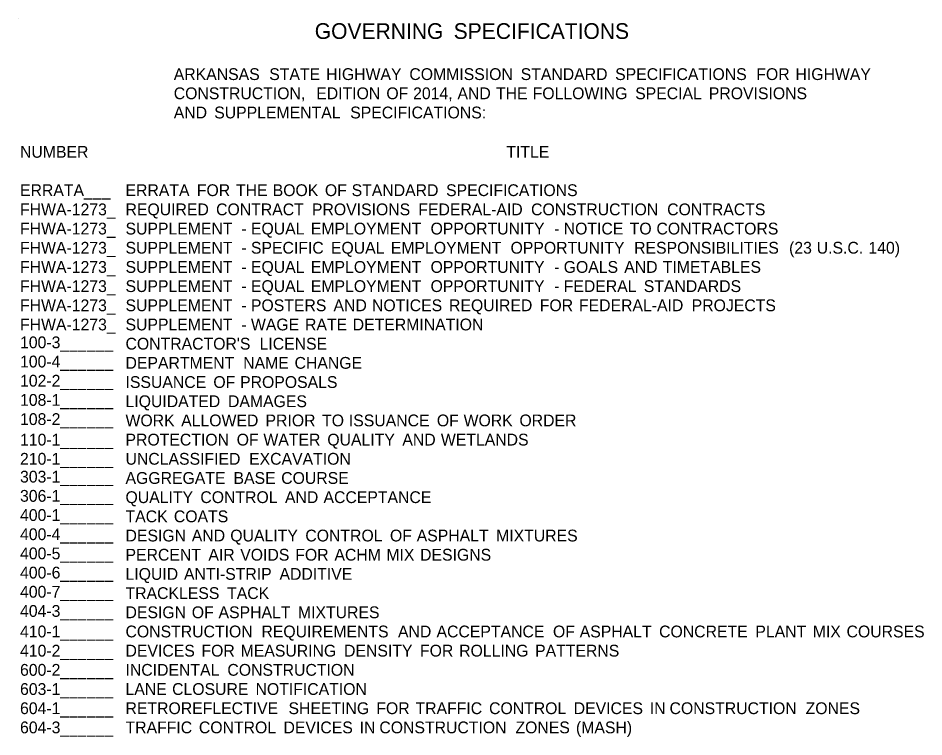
# Model space of a CAD drawing. Extents: x 1930579 to 1935504, y 596431 to 597414.
# Drawn here: x 1934071 to 1934624, y 596955 to 597393 of the extents above; entities that cross this region are included whole.
import ezdxf

# ---------------------------------------------------------------- set-up
doc = ezdxf.new("R2010")
doc.units = 0
doc.layers.add('Default', color=7, linetype='Continuous')
doc.layers.add('R_Border', color=7, linetype='Continuous')

msp = doc.modelspace()

# ---------------------------------------------------------------- linework, layer by layer
at = {"layer": 'R_Border'}
msp.add_line((1934071.42, 597393.18), (1934071.42, 597393.18), dxfattribs=at)

# ---------------------------------------------------------------- texts
at = {"layer": 'Default'}
for s, height, p in [('GOVERNING', 9.6, (1934252.37, 597380.48)), (' SPECIFICATIONS', 9.6, (1934333.54, 597380.48)), ('           ARKANSAS', 7.2, (1934136.94, 597355.42)), (' STATE', 7.2, (1934221.94, 597355.42)), (' HIGHWAY', 7.2, (1934256.63, 597355.42)), (' COMMISSION', 7.2, (1934307.41, 597355.42)), (' STANDARD', 7.2, (1934375.33, 597355.42)), (' SPECIFICATIONS', 7.2, (1934432.93, 597355.42)), (' FOR', 7.2, (1934519.05, 597355.42)), (' HIGHWAY', 7.2, (1934542.95, 597355.42)), ('           CONSTRUCTION,', 7.2, (1934136.94, 597343.72)), (' EDITION', 7.2, (1934250.61, 597343.72)), (' OF', 7.2, (1934293.38, 597343.72)), (' 2014,', 7.2, (1934309.69, 597343.72)), (' AND', 7.2, (1934336.75, 597343.72)), (' THE', 7.2, (1934360.25, 597343.72)), (' FOLLOWING', 7.2, (1934382.63, 597343.72)), (' SPECIAL', 7.2, (1934445.15, 597343.72)), (' PROVISIONS', 7.2, (1934490.08, 597343.72)), ('           AND', 7.2, (1934136.94, 597332.02)), (' SUPPLEMENTAL', 7.2, (1934188.37, 597332.02)), (' SPECIFICATIONS:', 7.2, (1934271.32, 597332.02)), ('NUMBER', 7.2, (1934072.59, 597308.04)), ('TITLE', 7.2, (1934369.21, 597308.04)), ('ERRATA___', 7.2, (1934072.59, 597284.64)), ('ERRATA', 7.2, (1934136.94, 597284.64)), (' FOR', 7.2, (1934177.77, 597284.64)), (' THE', 7.2, (1934201.67, 597284.64)), (' BOOK', 7.2, (1934224.04, 597284.64)), (' OF', 7.2, (1934255.89, 597284.64)), (' STANDARD', 7.2, (1934272.19, 597284.64)), (' SPECIFICATIONS', 7.2, (1934329.79, 597284.64)), ('FHWA-1273_', 7.2, (1934072.59, 597272.94)), ('REQUIRED', 7.2, (1934136.94, 597272.94)), (' CONTRACT', 7.2, (1934189.51, 597272.94)), (' PROVISIONS', 7.2, (1934247.99, 597272.94)), (' FEDERAL-AID', 7.2, (1934312.88, 597272.94)), (' CONSTRUCTION', 7.2, (1934381.65, 597272.94)), (' CONTRACTS', 7.2, (1934464.67, 597272.94)), ('FHWA-1273_', 7.2, (1934072.59, 597261.24)), ('SUPPLEMENT', 7.2, (1934136.94, 597261.24)), (' EQUAL', 7.2, (1934210.77, 597261.24)), (' EMPLOYMENT', 7.2, (1934247.32, 597261.24)), (' OPPORTUNITY', 7.2, (1934320.34, 597261.24)), (' NOTICE', 7.2, (1934401.56, 597261.24)), (' TO', 7.2, (1934441.82, 597261.24)), (' CONTRACTORS', 7.2, (1934458.14, 597261.24)), (' -', 7.2, (1934204.95, 597261.24)), (' -', 7.2, (1934395.73, 597261.24)), ('FHWA-1273_', 7.2, (1934072.59, 597249.54)), ('SUPPLEMENT', 7.2, (1934136.94, 597249.54)), (' -', 7.2, (1934204.95, 597249.54)), (' SPECIFIC', 7.2, (1934210.77, 597249.54)), (' EQUAL', 7.2, (1934259.57, 597249.54)), (' EMPLOYMENT', 7.2, (1934296.11, 597249.54)), (' OPPORTUNITY', 7.2, (1934369.14, 597249.54)), (' RESPONSIBILITIES', 7.2, (1934444.52, 597249.54)), (' (23', 7.2, (1934539.04, 597249.54)), (' U.S.C.', 7.2, (1934555.91, 597249.54)), (' 140)', 7.2, (1934587.45, 597249.54)), ('FHWA-1273_', 7.2, (1934072.59, 597237.84)), ('SUPPLEMENT', 7.2, (1934136.94, 597237.84)), (' -', 7.2, (1934204.95, 597237.84)), (' EQUAL', 7.2, (1934210.77, 597237.84)), (' EMPLOYMENT', 7.2, (1934247.32, 597237.84)), (' OPPORTUNITY', 7.2, (1934320.34, 597237.84)), (' -', 7.2, (1934395.73, 597237.84)), (' GOALS', 7.2, (1934401.56, 597237.84)), (' AND', 7.2, (1934438.49, 597237.84)), (' TIMETABLES', 7.2, (1934461.99, 597237.84)), ('FHWA-1273_', 7.2, (1934072.59, 597226.14)), ('SUPPLEMENT', 7.2, (1934136.94, 597226.14)), (' EQUAL', 7.2, (1934210.77, 597226.14)), (' EMPLOYMENT', 7.2, (1934247.32, 597226.14)), (' OPPORTUNITY', 7.2, (1934320.34, 597226.14)), (' FEDERAL', 7.2, (1934401.56, 597226.14)), (' STANDARDS', 7.2, (1934450.4, 597226.14)), (' -', 7.2, (1934204.95, 597226.14)), (' -', 7.2, (1934395.73, 597226.14)), ('FHWA-1273_', 7.2, (1934072.59, 597214.44)), ('SUPPLEMENT', 7.2, (1934136.94, 597214.44)), (' POSTERS', 7.2, (1934210.77, 597214.44)), (' AND', 7.2, (1934261.13, 597214.44)), (' NOTICES', 7.2, (1934284.62, 597214.44)), (' REQUIRED', 7.2, (1934331.61, 597214.44)), (' FOR', 7.2, (1934386.97, 597214.44)), (' FEDERAL-AID', 7.2, (1934410.87, 597214.44)), (' PROJECTS', 7.2, (1934479.64, 597214.44)), (' -', 7.2, (1934204.95, 597214.44)), ('FHWA-1273_', 7.2, (1934072.59, 597202.74)), ('SUPPLEMENT', 7.2, (1934136.94, 597202.74)), (' WAGE', 7.2, (1934210.77, 597202.74)), (' RATE', 7.2, (1934243.77, 597202.74)), (' DETERMINATION', 7.2, (1934272.86, 597202.74)), (' -', 7.2, (1934204.95, 597202.74)), ('100-3______', 7.2, (1934072.59, 597191.85)), ("CONTRACTOR'S", 7.2, (1934136.94, 597191.04)), (' LICENSE', 7.2, (1934216.03, 597191.04)), ('100-4______', 7.2, (1934072.59, 597180.15)), ('DEPARTMENT', 7.2, (1934136.94, 597179.34)), (' NAME', 7.2, (1934206.06, 597179.34)), (' CHANGE', 7.2, (1934237.38, 597179.34)), ('102-2______', 7.2, (1934072.59, 597168.45)), ('ISSUANCE', 7.2, (1934136.94, 597167.64)), (' OF', 7.2, (1934187.84, 597167.64)), (' PROPOSALS', 7.2, (1934204.15, 597167.64)), ('108-1______', 7.2, (1934072.59, 597156.75)), ('LIQUIDATED', 7.2, (1934136.94, 597155.94)), (' DAMAGES', 7.2, (1934196.78, 597155.94)), ('108-2______', 7.2, (1934072.59, 597145.05)), ('WORK', 7.2, (1934136.94, 597144.24)), (' ALLOWED', 7.2, (1934168.22, 597144.24)), (' PRIOR', 7.2, (1934219.67, 597144.24)), (' TO', 7.2, (1934254.18, 597144.24)), (' ISSUANCE', 7.2, (1934270.5, 597144.24)), (' OF', 7.2, (1934324.19, 597144.24)), (' WORK', 7.2, (1934340.5, 597144.24)), (' ORDER', 7.2, (1934374.56, 597144.24)), ('110-1______', 7.2, (1934072.59, 597132.54)), ('PROTECTION', 7.2, (1934136.94, 597132.54)), (' OF', 7.2, (1934202.08, 597132.54)), (' WATER', 7.2, (1934218.38, 597132.54)), (' QUALITY', 7.2, (1934257.37, 597132.54)), (' AND', 7.2, (1934303.13, 597132.54)), (' WETLANDS', 7.2, (1934326.63, 597132.54)), ('210-1______', 7.2, (1934072.59, 597120.84)), ('UNCLASSIFIED', 7.2, (1934136.94, 597120.84)), (' EXCAVATION', 7.2, (1934209.64, 597120.84)), ('303-1______', 7.2, (1934072.59, 597109.95)), ('AGGREGATE', 7.2, (1934136.94, 597109.14)), (' BASE', 7.2, (1934200.14, 597109.14)), (' COURSE', 7.2, (1934229.24, 597109.14)), ('306-1______', 7.2, (1934072.59, 597098.25)), ('QUALITY', 7.2, (1934136.94, 597097.44)), (' CONTROL', 7.2, (1934179.91, 597097.44)), (' AND', 7.2, (1934231.54, 597097.44)), (' ACCEPTANCE', 7.2, (1934255.03, 597097.44)), ('400-1______', 7.2, (1934072.59, 597086.55)), ('TACK', 7.2, (1934136.94, 597085.74)), (' COATS', 7.2, (1934163.76, 597085.74)), ('400-4______', 7.2, (1934072.59, 597074.85)), ('DESIGN', 7.2, (1934136.94, 597074.04)), (' AND', 7.2, (1934174.69, 597074.04)), (' QUALITY', 7.2, (1934198.19, 597074.04)), (' CONTROL', 7.2, (1934243.95, 597074.04)), (' OF', 7.2, (1934295.58, 597074.04)), (' ASPHALT', 7.2, (1934311.88, 597074.04)), (' MIXTURES', 7.2, (1934360.32, 597074.04)), ('400-5______', 7.2, (1934072.59, 597063.15)), ('PERCENT', 7.2, (1934136.94, 597062.34)), (' VOIDS', 7.2, (1934204.24, 597062.34)), (' FOR', 7.2, (1934237.82, 597062.34)), (' ACHM', 7.2, (1934261.71, 597062.34)), (' DESIGNS', 7.2, (1934313.98, 597062.34)), (' AIR', 7.2, (1934184.82, 597062.34)), (' MIX', 7.2, (1934293.37, 597062.34)), ('400-6______', 7.2, (1934072.59, 597051.45)), ('LIQUID', 7.2, (1934136.94, 597050.64)), (' ANTI-STRIP', 7.2, (1934169.94, 597050.64)), (' ADDITIVE', 7.2, (1934228.19, 597050.64)), ('400-7______', 7.2, (1934072.59, 597039.75)), ('TRACKLESS', 7.2, (1934136.94, 597038.94)), (' TACK', 7.2, (1934196.24, 597038.94)), ('404-3______', 7.2, (1934072.59, 597028.05)), ('DESIGN', 7.2, (1934136.94, 597027.24)), (' OF', 7.2, (1934174.69, 597027.24)), (' ASPHALT', 7.2, (1934191, 597027.24)), (' MIXTURES', 7.2, (1934239.44, 597027.24)), ('410-1______', 7.2, (1934072.59, 597015.54)), ('CONSTRUCTION', 7.2, (1934136.94, 597015.54)), (' REQUIREMENTS', 7.2, (1934217.16, 597015.54)), (' AND', 7.2, (1934300.48, 597015.54)), (' ACCEPTANCE', 7.2, (1934323.98, 597015.54)), (' OF', 7.2, (1934395.01, 597015.54)), (' ASPHALT', 7.2, (1934411.31, 597015.54)), (' CONCRETE', 7.2, (1934459.75, 597015.54)), (' PLANT', 7.2, (1934518.47, 597015.54)), (' MIX', 7.2, (1934553.48, 597015.54)), (' COURSES', 7.2, (1934574.09, 597015.54)), ('410-2______', 7.2, (1934072.59, 597003.84)), ('DEVICES', 7.2, (1934136.94, 597003.84)), (' FOR', 7.2, (1934180.59, 597003.84)), (' MEASURING', 7.2, (1934204.48, 597003.84)), (' DENSITY', 7.2, (1934267.57, 597003.84)), (' FOR', 7.2, (1934313.9, 597003.84)), (' ROLLING', 7.2, (1934337.79, 597003.84)), (' PATTERNS', 7.2, (1934384.11, 597003.84)), ('600-2______', 7.2, (1934072.59, 596992.14)), ('INCIDENTAL', 7.2, (1934136.94, 596992.14)), (' CONSTRUCTION', 7.2, (1934196.4, 596992.14)), ('603-1______', 7.2, (1934072.59, 596980.44)), ('LANE', 7.2, (1934136.94, 596980.44)), (' CLOSURE', 7.2, (1934162.69, 596980.44)), (' NOTIFICATION', 7.2, (1934213.58, 596980.44)), ('604-1______', 7.2, (1934072.59, 596968.74)), ('RETROREFLECTIVE', 7.2, (1934136.94, 596968.74)), (' SHEETING', 7.2, (1934233.68, 596968.74)), (' FOR', 7.2, (1934287.27, 596968.74)), (' TRAFFIC', 7.2, (1934311.16, 596968.74)), (' CONTROL', 7.2, (1934356.03, 596968.74)), (' DEVICES', 7.2, (1934407.66, 596968.74)), (' IN', 7.2, (1934454.09, 596968.74)), (' CONSTRUCTION', 7.2, (1934466.12, 596968.74)), (' ZONES', 7.2, (1934549.14, 596968.74)), ('604-3______', 7.2, (1934072.59, 596957.04)), ('TRAFFIC', 7.2, (1934136.94, 596957.04)), (' CONTROL', 7.2, (1934179.02, 596957.04)), (' DEVICES', 7.2, (1934230.64, 596957.04)), (' IN', 7.2, (1934277.08, 596957.04)), (' CONSTRUCTION', 7.2, (1934289.11, 596957.04)), (' ZONES', 7.2, (1934372.12, 596957.04)), (' (MASH)', 7.2, (1934409.05, 596957.04))]:
    msp.add_text(s, height=height, dxfattribs=at).set_placement(p)

doc.saveas('drawing.dxf')
